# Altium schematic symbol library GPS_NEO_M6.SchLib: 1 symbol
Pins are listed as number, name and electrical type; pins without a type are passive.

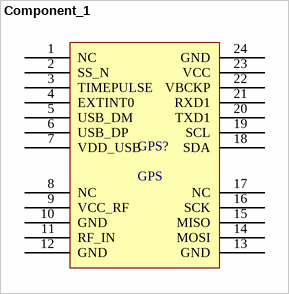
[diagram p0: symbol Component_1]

## Component_1
designator GPS?, comment GPS
footprint PCBComponent_1
footprint PCBComponent_1
pins: 1 NC, 2 SS_N, 3 TIMEPULSE, 4 EXTINT0, 5 USB_DM, 6 USB_DP, 7 VDD_USB, 8 NC, 9 VCC_RF, 10 GND, 11 RF_IN, 12 GND, 13 GND, 14 MOSI, 15 MISO, 16 SCK, 17 NC, 18 SDA, 19 SCL, 20 TXD1, 21 RXD1, 22 VBCKP, 23 VCC, 24 GND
